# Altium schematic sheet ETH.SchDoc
size A3; SheetNumber: 1; SheetTotal: 4
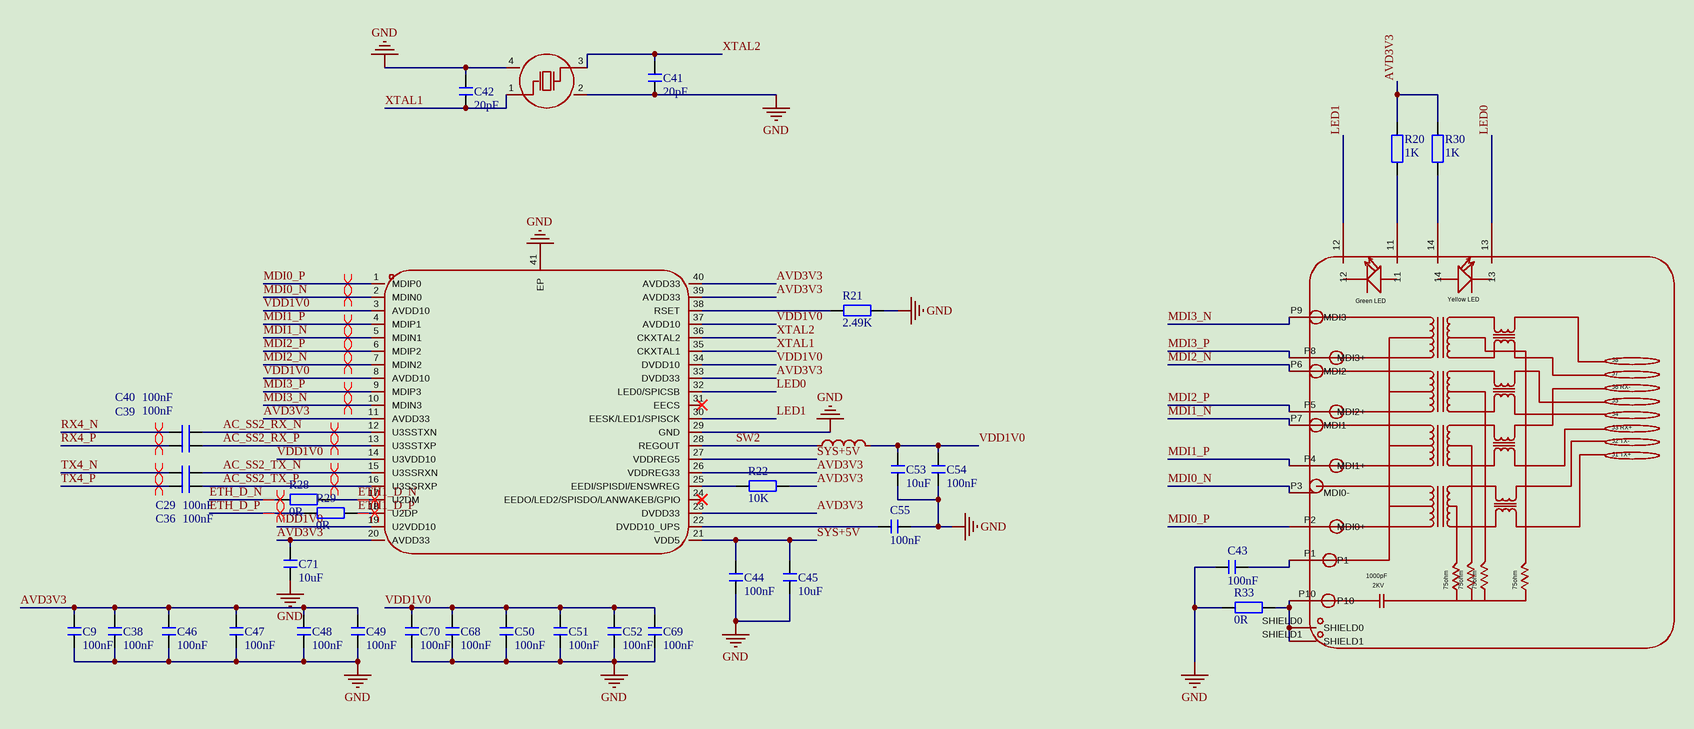
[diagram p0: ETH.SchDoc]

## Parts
C9  100nF  [C 0402_L]
C29  100nF  [C 0402_L]
C36  100nF  [C 0402_L]
C38  100nF  [C 0402_L]
C39  100nF  [C 0402_L]
C40  100nF  [C 0402_L]
C41  20pF  [C 0603_L]
C42  20pF  [C 0603_L]
C43  100nF  [C 0805_L]
C44  100nF  [C 0402_L]
C45  10uF  [C 0805_L]
C46  100nF  [C 0402_L]
C47  100nF  [C 0402_L]
C48  100nF  [C 0402_L]
C49  100nF  [C 0402_L]
C50  100nF  [C 0402_L]
C51  100nF  [C 0402_L]
C52  100nF  [C 0402_L]
C53  10uF  [C 0805_L]
C54  100nF  [C 0402_L]
C55  100nF  [C 0402_L]
C68  100nF  [C 0402_L]
C69  100nF  [C 0402_L]
C70  100nF  [C 0402_L]
C71  10uF  [C 0805_L]
L3  smms252012-2r2m  [IND-SMD_L2.5-W2.0_AFE252010S]  (value not drawn)
R20  1K  [R 0805_L]
R21  2.49K  [R 0402_L]
R22  10K  [R 0402_L]
R28  0R  [R 0201_L]
R29  0R  [R 0201_L]
R30  1K  [R 0805_L]
R33  0R  [R 0402_L]
RJ1  hr911130a  [RJ45-TH_HR911130A]  (value not drawn)
U6  rtl8153b-vb-cg  [QFN-40_L5.0-W5.0-P0.40-BL-EP3.7]  (value not drawn)
X2  x322525mob4si  [CRYSTAL-SMD_4P-L3.2-W2.5-BL]  (value not drawn)

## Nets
GND: C9.1 C38.1 C41.1 C42.2 C43.2 C44.1 C45.1 C46.1 C47.1 C48.1 C49.1 C50.1 C51.1 C52.1 C53.1 C54.1 C55.1 C68.1 C69.1 C70.1 C71.1 R21.1 R33.2 U6.29(GND) U6.41(EP) X2.2(GND) X2.4(GND)
AC_SS2_RX_N: C39.2 U6.12(U3SSTXN)
AC_SS2_RX_P: C40.2 U6.13(U3SSTXP)
AC_SS2_TX_N: C36.2 U6.15(U3SSRXN)
AC_SS2_TX_P: C29.2 U6.16(U3SSRXP)
AVD3V3: C9.2 C38.2 C46.2 C47.2 C48.2 C49.2 C71.2 R20.2 R22.1 R30.2 U6.11(AVDD33) U6.20(AVDD33) U6.23(DVDD33) U6.26(VDDREG33) U6.33(DVDD33) U6.39(AVDD33) U6.40(AVDD33)
ETH1_D_N: R28.1 U6.17(U2DM)
ETH1_D_P: R29.1 U6.18(U2DP)
ETH_D_N: R28.2
ETH_D_P: R29.2
LED0: RJ1.13 U6.32(LED0/SPICSB)
LED1: RJ1.12 U6.30(EESK/LED1/SPISCK)
MDI0_N: RJ1.P3(MDI0-) U6.2(MDIN0)
MDI0_P: RJ1.P2(MDI0+) U6.1(MDIP0)
MDI1_N: RJ1.P7(MDI1-) U6.5(MDIN1)
MDI1_P: RJ1.P4(MDI1+) U6.4(MDIP1)
MDI2_N: RJ1.P6(MDI2-) U6.7(MDIN2)
MDI2_P: RJ1.P5(MDI2+) U6.6(MDIP2)
MDI3_N: RJ1.P9(MDI3-) U6.10(MDIN3)
MDI3_P: RJ1.P8(MDI3+) U6.9(MDIP3)
RX4_N: C39.1
RX4_P: C40.1
SW2: L3.1 U6.28(REGOUT)
SYS+5V: C44.2 C45.2 U6.21(VDD5) U6.27(VDDREG5)
TX4_N: C36.1
TX4_P: C29.1
VDD1V0: C50.2 C51.2 C52.2 C53.2 C54.2 C68.2 C69.2 C70.2 L3.2 U6.3(AVDD10) U6.8(AVDD10) U6.14(U3VDD10) U6.19(U2VDD10) U6.34(DVDD10) U6.37(AVDD10)
XTAL1: C42.1 U6.35(CKXTAL1) X2.1(OSC1)
XTAL2: C41.2 U6.36(CKXTAL2) X2.3(OSC2)
NetC43_1: C43.1 RJ1.P1
NetC55_2: C55.2 U6.22(DVDD10_UPS)
NetR20_1: R20.1 RJ1.11
NetR21_2: R21.2 U6.38(RSET)
NetR22_2: R22.2 U6.25(EEDI/SPISDI/ENSWREG)
NetR30_1: R30.1 RJ1.14
NetR33_1: R33.1 RJ1.P10 RJ1.SHIELD0 RJ1.SHIELD1

Not connected (* = marked no-connect by the designer): U6 24(EEDO/LED2/SPISDO/LANWAKEB/GPIO)* 31(EECS)*

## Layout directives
differential pair; differential pair class 90ohm: AC_SS2_RX_N, AC_SS2_RX_P, AC_SS2_TX_N, AC_SS2_TX_P, ETH1_D_N, ETH1_D_P, ETH_D_N, ETH_D_P, RX4_N, RX4_P, TX4_N, TX4_P
differential pair; differential pair class 100ohm: MDI0_N, MDI0_P, MDI1_N, MDI1_P, MDI2_N, MDI2_P, MDI3_N, MDI3_P

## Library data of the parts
C9 C29 C36 C38-C55 C68-C71 = C: 无极性贴片电容; 版权归属: 源创客; 材质: X7R
L3 = smms252012-2r2m: 电感值:2.2uH;精度:±20%;额定电流:3A;饱和电流(Isat):3.8A;类型:磁胶屏蔽电感;; Manufacturer: SXN(顺翔诺); AddInBom: yes; ModelId: 94dc9c04db714140b05057b13e968e87; ModelTransform: 98.425,78.74,0,0,0,0,0,0,0; Value: 2.2uH; Tolerance: ±20%; Current Rating: 3A; Current - Saturation(Isat): 3.8A; DC Resistance(DCR): 55mΩ; Type: 磁胶屏蔽电感
R20-R22 R28-R30 R33 = R: 贴片电阻; 版权归属: 源创客
RJ1 = hr911130a: 连接器类型:RJ45插座;安装方式:弯插;端口数量:1;LED:带LED;屏蔽:有屏蔽;等级:-;触头材质:磷青铜;触头镀层:金;工作温度:0℃~+70℃;; Manufacturer: HANRUN(汉仁); AddInBom: yes; ModelId: 21112b2bcfef4316930bd636ff253b92; ModelTransform: 635.432,838.62,0,180,0,0,0,88.937,-157.48; Connector Type: RJ45插座; Number of Ports: 1; LED: 带LED; Shielding: 有屏蔽; PoE: 不带PoE; Supplementary Features: 带十字脚
U6 = rtl8153b-vb-cg: 类型:-;端口数量:1;MAC接口:-;; Manufacturer: REALTEK(瑞昱); AddInBom: yes; ModelId: f658c93bb71c4057b80d8d21cfcdd805; ModelName: QFN-40_L5.0-W5.0-H0.9-P0.4-BL-EP; ModelTransform: 196.85,196.85,0,90,0,0,0,0,0; Number of ports: 1; Ethernet Speed Standards: 1000BASE-T；10BASE-T；100BASE-TX; Data Rate: 10Mbit/s；100Mbit/s；1Gbit/s; Voltage - Supply: 3.3V；1V；5V
X2 = x322525mob4si: 晶振类型:贴片晶振;频率:25MHz;常温频差:±10ppm;负载电容:12pF;频率稳定度:±20ppm;; Manufacturer: YXC(扬兴晶振); AddInBom: yes; ModelId: ff2dfd5650294453a14147960efe1838; ModelTransform: 125.984,98.425,0,0,0,0,0,0,0; Value: 25MHz; Normal temperature Frequency Tolerance: ±10ppm; Load Capacitance: 12pF; Frequency Stability: ±20ppm; Equivalent Series Resistance(ESR): 50Ω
